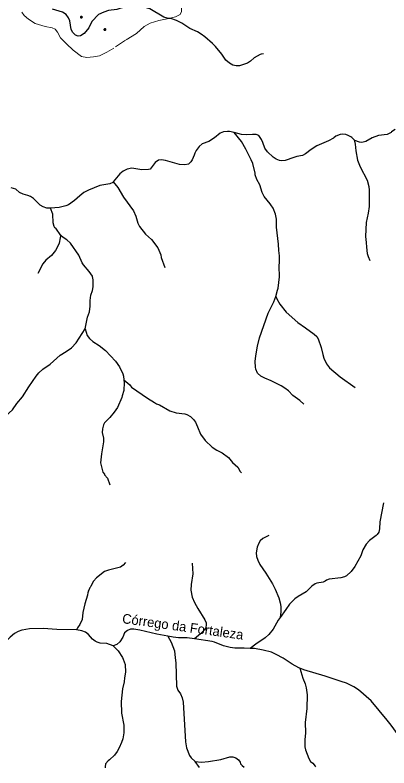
# Model space of a CAD drawing. Extents: x 396 to 422.2, y 7649.8 to 7677.6.
# Drawn here: x 413.01 to 416.1, y 7649.93 to 7656.16 of the extents above; entities that cross this region are included whole.
import ezdxf
from ezdxf.enums import TextEntityAlignment as Align

# ---------------------------------------------------------------- set-up
doc = ezdxf.new("R2010")
doc.units = 0
doc.header["$LTSCALE"] = 0.032
doc.header["$PDMODE"] = 32
doc.header["$PDSIZE"] = 0.016
doc.linetypes.add('SHORT_DASHED', pattern=[2.7, 1.5, -1.2])
doc.layers.add('21', color=7, linetype='SHORT_DASHED', lineweight=13)
doc.layers.add('7', color=7, linetype='Continuous', lineweight=25)
doc.layers.add('61', color=7, linetype='Continuous')

msp = doc.modelspace()

# ---------------------------------------------------------------- linework, layer by layer
at = {"layer": '21'}
for points in [[(414.4702, 7656.5802), (414.5404, 7656.574), (414.5619, 7656.5641), (414.5652, 7656.5607), (414.5619, 7656.5475), (414.5371, 7656.5277), (414.5091, 7656.5046), (414.4727, 7656.465), (414.4562, 7656.4336), (414.4397, 7656.3956), (414.4232, 7656.3626), (414.4034, 7656.3131), (414.3935, 7656.2668), (414.3885, 7656.2239), (414.3869, 7656.1925), (414.377, 7656.1678), (414.3654, 7656.1612), (414.339, 7656.148), (414.2845, 7656.1346)], [(414.2845, 7656.1346), (414.2003, 7656.1166), (414.1276, 7656.0951), (414.0798, 7656.0687), (414.0154, 7656.0093), (413.9245, 7655.9531), (413.8271, 7655.8887), (413.7693, 7655.854), (413.7099, 7655.8243), (413.6604, 7655.8161), (413.6042, 7655.8111), (413.5613, 7655.8194), (413.4919, 7655.8706), (413.4358, 7655.9234), (413.3879, 7655.9729), (413.3615, 7656.0192), (413.3433, 7656.0456), (413.3186, 7656.0555), (413.2608, 7656.067), (413.1766, 7656.0935), (413.1221, 7656.1281), (413.0858, 7656.1579), (413.0659, 7656.1859)]]:
    msp.add_lwpolyline(points, dxfattribs=at)
for p in [(413.5596, 7656.1447), (413.7545, 7656.0423)]:
    msp.add_point(p, dxfattribs=at)
at = {"layer": '7'}
for p, q in [((413.8237, 7654.7822), (413.8193, 7654.7768)), ((414.5363, 7649.9311), (414.5017, 7649.9811))]:
    msp.add_line(p, q, dxfattribs=at)
for points in [[(413.9228, 7656.2307), (413.8529, 7656.2094), (413.7829, 7656.1996), (413.7457, 7656.1866), (413.7015, 7656.1669), (413.6468, 7656.1099), (413.6203, 7656.0572), (413.5822, 7656.0083), (413.5513, 7655.991), (413.5334, 7655.9885), (413.5117, 7655.9945), (413.4901, 7656.0186), (413.4758, 7656.0416), (413.4635, 7656.1151), (413.4526, 7656.1387), (413.4335, 7656.1669), (413.4043, 7656.1849), (413.32, 7656.2114)], [(414.2845, 7656.1346), (414.2699, 7656.1363), (414.2419, 7656.1441), (414.1271, 7656.213), (414.063, 7656.2338), (414.0302, 7656.2508)], [(415.0654, 7655.8421), (415.0481, 7655.8375), (415.04, 7655.8353), (414.9899, 7655.8076), (414.9595, 7655.78), (414.9346, 7655.7632), (414.8692, 7655.7407), (414.8416, 7655.7407), (414.8122, 7655.7472), (414.7858, 7655.7639), (414.7554, 7655.7899), (414.7214, 7655.8386), (414.6707, 7655.9024), (414.6446, 7655.9257), (414.5823, 7655.9813), (414.5516, 7656.0042), (414.5205, 7656.0227), (414.4584, 7656.0517), (414.3912, 7656.0949), (414.3471, 7656.117), (414.2997, 7656.1328), (414.2845, 7656.1346)], [(416.1553, 7655.2138), (416.1271, 7655.1953), (416.1233, 7655.1895), (416.0889, 7655.1738), (416.0187, 7655.165), (415.966, 7655.1467), (415.9134, 7655.114), (415.8804, 7655.1068), (415.8604, 7655.1083), (415.8232, 7655.1228), (415.8159, 7655.13)], [(414.8229, 7655.1887), (414.7862, 7655.1979), (414.7676, 7655.1992), (414.7348, 7655.1945), (414.7091, 7655.1836), (414.6624, 7655.1454), (414.614, 7655.116), (414.5587, 7655.0948), (414.5356, 7655.0738), (414.5098, 7655.0398), (414.4974, 7655.0186), (414.4917, 7655.0027), (414.4775, 7654.9632), (414.4662, 7654.9454), (414.4473, 7654.9273), (414.4162, 7654.9217), (414.3726, 7654.9248), (414.2552, 7654.9577), (414.2221, 7654.9623), (414.1978, 7654.9596), (414.1708, 7654.9418), (414.1283, 7654.8866), (414.1152, 7654.8818), (414.0605, 7654.8812), (413.9766, 7654.8929), (413.9394, 7654.8847), (413.9054, 7654.87), (413.8776, 7654.8481), (413.8237, 7654.7822)], [(415.169, 7653.8313), (415.1826, 7653.8844), (415.1867, 7653.9006), (415.1993, 7653.9931), (415.1969, 7654.0824), (415.2001, 7654.1186), (415.2001, 7654.1672), (415.1939, 7654.2137), (415.1921, 7654.2637), (415.1755, 7654.4062), (415.1746, 7654.4711), (415.1667, 7654.5146), (415.1463, 7654.5618), (415.128, 7654.5909), (415.1224, 7654.5979), (415.0727, 7654.6598), (415.0552, 7654.6913), (415.0351, 7654.7555), (415.0118, 7654.8002), (414.9976, 7654.8388), (414.9974, 7654.8523), (414.9783, 7654.9316), (414.9658, 7654.9628), (414.9204, 7655.0521), (414.8837, 7655.1159), (414.8229, 7655.1887)], [(415.8159, 7655.13), (415.7985, 7655.1471), (415.788, 7655.1534), (415.7682, 7655.1652), (415.7469, 7655.1729), (415.7242, 7655.1759), (415.6997, 7655.1729), (415.6652, 7655.1595), (415.6483, 7655.1445), (415.6463, 7655.1435), (415.6033, 7655.1209), (415.5071, 7655.0791), (415.4598, 7655.049), (415.413, 7655.0131), (415.3891, 7655.0002), (415.3428, 7654.9897), (415.3165, 7654.9838), (415.2452, 7654.9584), (415.2179, 7654.9543), (415.1995, 7654.9567), (415.1723, 7654.9676), (415.1469, 7654.985), (415.0991, 7655.0283), (415.0772, 7655.0592), (415.0624, 7655.1059), (415.0511, 7655.1303), (415.0275, 7655.1642), (415.0059, 7655.1721), (414.9765, 7655.1728), (414.9282, 7655.169), (414.8859, 7655.1729), (414.8229, 7655.1887)], [(415.8159, 7655.13), (415.8261, 7655.0939), (415.8302, 7655.0375), (415.8436, 7654.9602), (415.8652, 7654.9041), (415.9239, 7654.7947), (415.9371, 7654.7427), (415.9403, 7654.7133), (415.9402, 7654.5768), (415.9338, 7654.5214), (415.9155, 7654.4436), (415.9115, 7654.3287), (415.917, 7654.278), (415.9178, 7654.2394), (415.9243, 7654.188), (415.9315, 7654.1626), (415.9475, 7654.1298)], [(413.8193, 7654.7768), (413.7957, 7654.7651), (413.7136, 7654.751), (413.6176, 7654.7126), (413.5789, 7654.6914), (413.5455, 7654.6659), (413.5027, 7654.6256), (413.4523, 7654.5909), (413.4314, 7654.5823), (413.3751, 7654.5691), (413.3037, 7654.5639)], [(413.8237, 7654.7822), (413.8623, 7654.7341), (413.9089, 7654.6553), (413.9897, 7654.5401), (414.0101, 7654.4977), (414.0265, 7654.4393), (414.0394, 7654.4106), (414.0911, 7654.3472), (414.1392, 7654.3038), (414.193, 7654.2355), (414.2176, 7654.1765), (414.2209, 7654.1554), (414.2504, 7654.0708)], [(413.3037, 7654.5639), (413.275, 7654.5618), (413.2422, 7654.5738), (413.2199, 7654.5886), (413.1628, 7654.6423), (413.1394, 7654.6584), (413.1178, 7654.6683), (413.0769, 7654.6778), (413.0479, 7654.6934), (413.0181, 7654.7191), (412.9783, 7654.7302)], [(413.39, 7654.3379), (413.3471, 7654.3961), (413.3411, 7654.4004), (413.3352, 7654.4105), (413.3261, 7654.4413), (413.3228, 7654.5133), (413.3037, 7654.5639)], [(413.39, 7654.3379), (413.3833, 7654.3179), (413.3745, 7654.2722), (413.3623, 7654.2431), (413.3444, 7654.2123), (413.3137, 7654.1701), (413.2662, 7654.1313), (413.24, 7654.101), (413.2001, 7654.023)], [(413.5912, 7653.5629), (413.5917, 7653.5637), (413.6101, 7653.6589), (413.6267, 7653.7035), (413.633, 7653.7506), (413.6315, 7653.7996), (413.637, 7653.8415), (413.6512, 7653.8807), (413.6585, 7653.9105), (413.6569, 7653.9682), (413.652, 7653.9968), (413.6513, 7654.0011), (413.6248, 7654.0391), (413.576, 7654.093), (413.5654, 7654.1111), (413.5383, 7654.1733), (413.47, 7654.2719), (413.4391, 7654.3015), (413.4097, 7654.3204), (413.39, 7654.3379)], [(415.4008, 7652.9393), (415.3682, 7652.97), (415.3104, 7653.0114), (415.2722, 7653.0489), (415.2421, 7653.0732), (415.2125, 7653.0916), (415.1298, 7653.1333), (415.0766, 7653.1547), (415.044, 7653.1724), (415.0178, 7653.1964), (415.002, 7653.2308), (414.9992, 7653.245), (414.9984, 7653.294), (415.0031, 7653.341), (415.016, 7653.4196), (415.0323, 7653.4896), (415.1039, 7653.6926), (415.1532, 7653.788), (415.169, 7653.8313)], [(415.169, 7653.8313), (415.1768, 7653.8111), (415.2019, 7653.7686), (415.2533, 7653.7026), (415.351, 7653.6166), (415.4151, 7653.573), (415.4846, 7653.5199), (415.5074, 7653.4994), (415.5182, 7653.4801), (415.5444, 7653.4088), (415.5574, 7653.3506), (415.5672, 7653.3196), (415.5892, 7653.2727), (415.6124, 7653.2413), (415.7004, 7653.1661), (415.8262, 7653.0787)], [(412.7171, 7652.1064), (412.7443, 7652.185), (412.7581, 7652.237), (412.7631, 7652.267), (412.7868, 7652.3514), (412.7997, 7652.4418), (412.8091, 7652.479), (412.8388, 7652.646), (412.8653, 7652.7356), (412.8867, 7652.7863), (412.9339, 7652.8428), (412.9883, 7652.8926), (413.0263, 7652.9447), (413.0726, 7653.0011), (413.126, 7653.0845), (413.1866, 7653.1713), (413.2069, 7653.2004), (413.2412, 7653.2302), (413.3003, 7653.2714), (413.385, 7653.345), (413.4347, 7653.3755), (413.4773, 7653.4071), (413.5161, 7653.4482), (413.5912, 7653.5629)], [(413.5912, 7653.5629), (413.6083, 7653.5073), (413.6258, 7653.4837), (413.6531, 7653.4595), (413.7061, 7653.4263), (413.7596, 7653.3851), (413.7598, 7653.3849), (413.8422, 7653.296), (413.8764, 7653.2498), (413.9019, 7653.1896), (413.909, 7653.171), (413.9111, 7653.1414)], [(413.9111, 7653.1414), (413.913, 7653.1137), (413.9102, 7653.0595), (413.9099, 7653.0536), (413.897, 7653.009), (413.8953, 7652.9946), (413.858, 7652.9118), (413.8322, 7652.8727), (413.7943, 7652.8282), (413.7504, 7652.7846), (413.7423, 7652.7681), (413.7343, 7652.7362), (413.7328, 7652.7043), (413.7422, 7652.6576), (413.7439, 7652.6277), (413.7248, 7652.528), (413.7185, 7652.4545), (413.736, 7652.3753), (413.7498, 7652.359), (413.7511, 7652.3537), (413.7757, 7652.3282), (413.7958, 7652.2717)], [(413.9111, 7653.1414), (413.9608, 7653.0986), (413.9669, 7653.0904), (413.9742, 7653.0805), (414.1058, 7652.9883), (414.1638, 7652.9541), (414.1818, 7652.9434), (414.2061, 7652.9329), (414.2922, 7652.8842), (414.3438, 7652.8692), (414.4162, 7652.8591), (414.4329, 7652.8537), (414.4614, 7652.8372), (414.4886, 7652.8139), (414.5027, 7652.7914), (414.5213, 7652.7528), (414.5442, 7652.6924), (414.584, 7652.6397), (414.6416, 7652.5844), (414.6815, 7652.5583), (414.7243, 7652.5362), (414.7771, 7652.4976), (414.8108, 7652.4575), (414.853, 7652.417), (414.8728, 7652.3831), (414.8836, 7652.3706)], [(416.0599, 7652.1217), (416.0296, 7651.9649), (416.0263, 7651.9072), (416.0199, 7651.8804), (416.0077, 7651.8607), (415.9985, 7651.8513), (415.943, 7651.8116), (415.915, 7651.7789), (415.8893, 7651.732), (415.8718, 7651.6842), (415.8237, 7651.5957), (415.7931, 7651.5543), (415.7522, 7651.5181), (415.7363, 7651.5101), (415.7054, 7651.5028), (415.6104, 7651.4901), (415.5886, 7651.4832), (415.5777, 7651.475), (415.5592, 7651.4669), (415.5071, 7651.4567), (415.4932, 7651.4507), (415.466, 7651.432), (415.4205, 7651.385), (415.3528, 7651.3465), (415.3267, 7651.327), (415.2814, 7651.2847), (415.2528, 7651.2392), (415.2049, 7651.1725)], [(415.1101, 7651.8514), (415.0614, 7651.8272), (415.0398, 7651.8069), (415.028, 7651.7894), (415.015, 7651.7564), (415.0072, 7651.7096), (415.0087, 7651.6778), (415.019, 7651.6477), (415.0366, 7651.6122), (415.0851, 7651.5413), (415.1405, 7651.4506), (415.1628, 7651.4076), (415.1936, 7651.3364), (415.2048, 7651.2938), (415.2089, 7651.2647), (415.2097, 7651.2205), (415.2049, 7651.1725)], [(413.9234, 7651.6273), (413.9055, 7651.6055), (413.8839, 7651.5904), (413.8399, 7651.5774), (413.7837, 7651.5658), (413.7523, 7651.553), (413.6856, 7651.5004), (413.6597, 7651.4735), (413.6369, 7651.4331), (413.6335, 7651.4225), (413.6276, 7651.4157), (413.6273, 7651.4104), (413.6229, 7651.4065), (413.6225, 7651.4001), (413.6164, 7651.3901), (413.6163, 7651.3828), (413.6132, 7651.3805), (413.6096, 7651.3571), (413.5872, 7651.2854), (413.5717, 7651.2153), (413.5652, 7651.1575), (413.5479, 7651.1147), (413.5272, 7651.0884), (413.5185, 7651.0717)], [(414.4777, 7651.6241), (414.4831, 7651.5348), (414.4681, 7651.4462), (414.4648, 7651.3983), (414.4762, 7651.3407), (414.4966, 7651.2965), (414.5236, 7651.2475), (414.5824, 7651.1537), (414.5922, 7651.128), (414.5932, 7651.1156), (414.5892, 7651.086), (414.5789, 7651.07), (414.5452, 7651.0367), (414.4957, 7650.9955)], [(415.2049, 7651.1725), (415.1889, 7651.1502), (415.147, 7651.0771), (415.1114, 7651.0314), (415.0811, 7651.0033), (415.0042, 7650.9509), (414.956, 7650.9173)], [(413.5185, 7651.0717), (413.357, 7651.0745), (413.2422, 7651.0809), (413.1311, 7651.0785), (413.07, 7651.0677), (413.0676, 7651.0673), (413.0354, 7651.0561), (413.0064, 7651.0406), (412.9711, 7651.0107), (412.9408, 7650.9788), (412.9207, 7650.9466), (412.9041, 7650.904), (412.8908, 7650.8852), (412.8561, 7650.8604), (412.8071, 7650.8505), (412.7684, 7650.8539)], [(413.8218, 7650.9391), (413.7694, 7650.9579), (413.7148, 7650.9605), (413.6893, 7650.9678), (413.6726, 7650.9767), (413.651, 7650.9937), (413.6186, 7651.0315), (413.595, 7651.0524), (413.5632, 7651.0616), (413.5185, 7651.0717)], [(414.2744, 7651.0179), (414.1841, 7651.0354), (414.0441, 7651.0689), (413.9934, 7651.0761), (413.9672, 7651.0761), (413.9416, 7651.0665), (413.916, 7651.0472), (413.9033, 7651.01), (413.8775, 7650.9722), (413.8538, 7650.9502), (413.8218, 7650.9391)], [(414.2744, 7651.0179), (414.3039, 7650.9674), (414.3293, 7650.8972), (414.3363, 7650.838), (414.3413, 7650.7962), (414.3461, 7650.6037), (414.3578, 7650.5724), (414.3806, 7650.5395), (414.3929, 7650.5071), (414.401, 7650.4716), (414.4201, 7650.1419), (414.43, 7650.0929), (414.4543, 7650.0301), (414.4677, 7650.0107), (414.5017, 7649.9811)], [(414.4957, 7650.9955), (414.4349, 7651.0043), (414.362, 7651.0044), (414.3194, 7651.0092), (414.2744, 7651.0179)], [(414.956, 7650.9173), (414.908, 7650.9183), (414.8282, 7650.92), (414.7905, 7650.9246), (414.7346, 7650.9386), (414.6614, 7650.9691), (414.6431, 7650.9741), (414.4957, 7650.9955)], [(413.8218, 7650.9391), (413.8649, 7650.8978), (413.8993, 7650.8404), (413.9042, 7650.8282), (413.9225, 7650.7826), (413.9257, 7650.7204), (413.9162, 7650.6729), (413.9138, 7650.6411), (413.9012, 7650.583), (413.889, 7650.4781), (413.8923, 7650.3804), (413.9113, 7650.2802), (413.9114, 7650.2178), (413.902, 7650.1694), (413.8929, 7650.1389), (413.8732, 7650.0923), (413.8555, 7650.0621), (413.833, 7650.0336), (413.7936, 7649.9942), (413.7811, 7649.9857), (413.7583, 7649.961), (413.7567, 7649.935), (413.7562, 7649.927)], [(415.3669, 7650.7527), (415.3579, 7650.7563), (415.3048, 7650.7854), (415.2283, 7650.8368), (415.1727, 7650.8674), (415.1335, 7650.8846), (415.0626, 7650.9031), (414.9932, 7650.9166), (414.956, 7650.9173)], [(415.3669, 7650.7527), (415.3926, 7650.6703), (415.4107, 7650.6228), (415.4186, 7650.5912), (415.4266, 7650.5338), (415.425, 7650.4187), (415.4123, 7650.3045), (415.4146, 7650.2167), (415.4091, 7650.1609), (415.4091, 7650.1009), (415.4142, 7650.0774), (415.4424, 7650.0046), (415.4556, 7649.9817), (415.4746, 7649.9673), (415.4929, 7649.943), (415.4982, 7649.936)], [(416.2701, 7649.94), (416.2679, 7649.9531), (416.2597, 7650.0012), (416.2584, 7650.0088), (416.2545, 7650.0127), (416.2543, 7650.0241), (416.2375, 7650.0875), (416.1814, 7650.2015), (416.1225, 7650.2812), (416.0888, 7650.3225), (415.958, 7650.4826), (415.8534, 7650.5742), (415.8149, 7650.5989), (415.754, 7650.6302), (415.7081, 7650.6429), (415.5756, 7650.6875), (415.4004, 7650.7388), (415.3669, 7650.7527)], [(414.5017, 7649.9811), (414.553, 7649.9749), (414.6107, 7649.9796), (414.7143, 7649.9973), (414.788, 7650.0201), (414.812, 7650.0201), (414.8372, 7650.0106), (414.8596, 7649.9954), (414.8733, 7649.9745), (414.8776, 7649.9611), (414.89, 7649.9486), (414.9055, 7649.933)]]:
    msp.add_lwpolyline(points, dxfattribs=at)

# ---------------------------------------------------------------- texts
at = {"layer": '61'}
msp.add_text('Córrego da Fortaleza', height=0.08, rotation=352.166, dxfattribs=at).set_placement((414.3941, 7651.0579), align=Align.CENTER)

doc.saveas('drawing.dxf')
